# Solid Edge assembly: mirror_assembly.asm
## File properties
Author: Haley
Template: Iso Assembly.asm
Last saved by: Lee
Revision: 38
Application: Solid Edge
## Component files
mirror.asm
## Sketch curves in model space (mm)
line (61.4884, -5, 0) -> (61.4884, -5, 892.051)
line (0, -5, 0) -> (61.4884, -5, 0)
line (61.4884, 5, 0) -> (61.4884, 5, 912.05)
line (0, 5, 0) -> (61.4884, 5, 0)
line (59.7539, -5, 0) -> (59.7539, -5, 925.618)
line (0, -5, 0) -> (59.7539, -5, 0)
line (59.7539, 5, 0) -> (59.7539, 5, 945.618)
line (0, 5, 0) -> (59.7539, 5, 0)
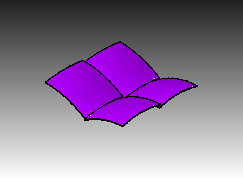
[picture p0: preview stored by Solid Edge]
